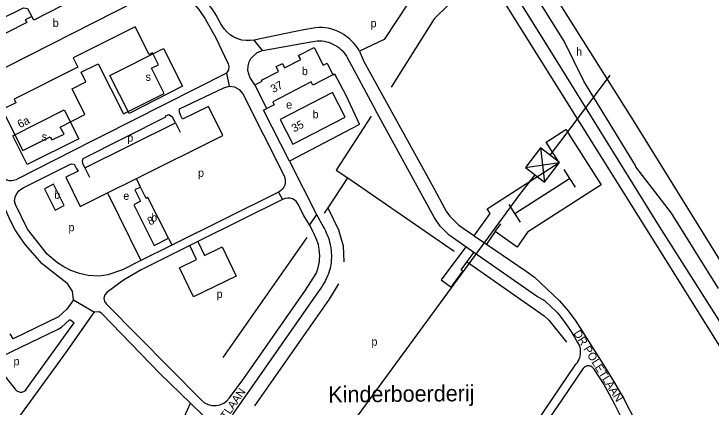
# Model space of a CAD drawing. Extents: x 158142 to 159655, y 385262 to 387204.
# Drawn here: x 159056.3 to 159402.4, y 386220.3 to 386415.6 of the extents above; entities that cross this region are included whole.
import ezdxf

# ---------------------------------------------------------------- set-up
doc = ezdxf.new("R2010")
doc.units = 0
for name, color, linetype in [('BLT_Basislijn', 7, 'Continuous'), ('BLT_Bebouwing', 7, 'Continuous'), ('BLT_Centroide', 7, 'Continuous'), ('BLT_Hoogspanningsmast_en_leidingen', 7, 'Continuous'), ('BLT_Huisnummer', 7, 'Continuous'), ('BLT_Huisnummer_zonder_bebouwing', 7, 'Continuous'), ('BLT_Plantopo', 7, 'Continuous'), ('BLT_Straatnaam_verkleind', 7, 'Continuous'), ('BLT_Terrein_beschrifting', 7, 'Continuous'), ('BLT_Vlakafsluiter', 7, 'Continuous')]:
    doc.layers.add(name, color=color, linetype=linetype)

msp = doc.modelspace()

# ---------------------------------------------------------------- linework, layer by layer
at = {"layer": 'BLT_Basislijn'}
for p, q in [((159227.95, 386397.14), (159229.86, 386392.29)), ((159221.65, 386394.34), (159235.67, 386368.16)), ((159091.61, 386339.19), (159136.59, 386361.56)), ((159136.59, 386361.56), (159138.94, 386356.79)), ((159193.2, 386342.48), (159206.56, 386316.04)), ((159091.61, 386339.19), (159093.91, 386334.54)), ((159329.32, 386338.29), (159332.13, 386333.91)), ((159119.2, 386329.59), (159117.12, 386333.8)), ((159222, 386334.21), (159212.14, 386319.33)), ((159222.04, 386334.14), (159274.93, 386297.82)), ((159305.02, 386316.48), (159332.13, 386333.91)), ((159332.13, 386333.91), (159334.95, 386329.53)), ((159102.79, 386326.67), (159119.38, 386293.11)), ((159305.02, 386316.48), (159302.2, 386320.86)), ((159212.14, 386319.33), (159210.35, 386316.62)), ((159307.83, 386312.1), (159305.02, 386316.48)), ((159295.31, 386307.53), (159298.04, 386311.37)), ((159295.31, 386307.53), (159290.87, 386301.25)), ((159133.08, 386304.14), (159134.75, 386300.77)), ((159160.16, 386244.92), (159201.9, 386304.56)), ((159284.86, 386305.35), (159290.87, 386301.25)), ((159147.69, 386302.57), (159143.71, 386300.59)), ((159284.71, 386297.1), (159280.61, 386299.95)), ((159278.34, 386288.55), (159284.71, 386297.1)), ((159062.18, 386228.82), (159086.31, 386262.11)), ((159049.87, 386238.11), (159056.95, 386229.28)), ((159344.23, 386239.16), (159349.21, 386231.63))]:
    msp.add_line(p, q, dxfattribs=at)
for points in [[(159478.02, 386149.53), (159467.1, 386166.67), (159451.19, 386191.65), (159448.58, 386196.2), (159403.98, 386267.32), (159376.84, 386309.95), (159320.35, 386401.06), (159194.99, 386601.74), (159190.31, 386604.18), (159180.82, 386620.38), (159176.63, 386631.64), (159172.66, 386639.08), (159146.46, 386681.4), (159151.12, 386684.55)], [(159413.02, 386283.52), (159409.77, 386288.65), (159364.7, 386361.34), (159326.64, 386421.78), (159323.99, 386426.39), (159205.26, 386616.42)], [(159406.2, 386279.27), (159382.73, 386316.66), (159365.07, 386339.65), (159364.85, 386340.38), (159339.3, 386382.12), (159329.59, 386402.01), (159197.96, 386612.2)], [(159115.71, 386445.71), (159116.77, 386445.89), (159117.81, 386445.92), (159118.97, 386445.78), (159120.27, 386445.46), (159132.43, 386434.32), (159132.87, 386433.9), (159140.84, 386426.2), (159148.13, 386417.86), (159151.35, 386413.14), (159156.54, 386403.77)], [(159283.65, 386446.69), (159288.31, 386439.83), (159375.73, 386300.12)], [(159159.7, 386409.64), (159159.41, 386410.19), (159159.12, 386410.72), (159158.09, 386412.56), (159156.72, 386414.9), (159155.38, 386417.04), (159153.14, 386420.28), (159149.94, 386424.39), (159148.22, 386426.41), (159146.03, 386428.81), (159143.45, 386431.45)], [(159251.36, 386433.07), (159252.44, 386421.45), (159240.13, 386402.93), (159227.95, 386397.14)], [(159277.97, 386429.97), (159272.13, 386420.08), (159264.98, 386413.18), (159243.67, 386379.17)], [(159023.64, 386400.21), (159061.09, 386418.61), (159063, 386418.33), (159065.21, 386414.36)], [(159175.58, 386402.58), (159173.63, 386402.31), (159171.59, 386402.31), (159169.53, 386402.59), (159167.49, 386403.17), (159165.55, 386404.04), (159163.76, 386405.16), (159162.17, 386406.5), (159160.81, 386408.02), (159159.7, 386409.64)], [(159206.06, 386408.7), (159200.25, 386407.61), (159195.32, 386406.62), (159179.43, 386403.35), (159175.58, 386402.58)], [(159220.05, 386405.32), (159218.68, 386406.17), (159217.23, 386406.91), (159215.72, 386407.54), (159214.16, 386408.05), (159212.55, 386408.44), (159210.93, 386408.7), (159209.29, 386408.83), (159207.67, 386408.83), (159206.06, 386408.7)], [(159156.54, 386403.77), (159160.84, 386394.55), (159162.74, 386390.86), (159162.98, 386389.41), (159162.93, 386387.85), (159161.92, 386386.1)], [(159227.95, 386397.14), (159227.28, 386398.21), (159226.54, 386399.25), (159225.75, 386400.26), (159224.91, 386401.22), (159224.02, 386402.14), (159223.09, 386403.01), (159222.11, 386403.84), (159221.1, 386404.61), (159220.05, 386405.32)], [(159179.8, 386397.43), (159204.7, 386401.94)], [(159204.7, 386401.94), (159205.83, 386402.11), (159206.96, 386402.2), (159208.1, 386402.22), (159209.24, 386402.15), (159210.37, 386402.01), (159211.49, 386401.78), (159212.59, 386401.48), (159213.66, 386401.1), (159214.7, 386400.65), (159215.71, 386400.12), (159216.68, 386399.53), (159217.61, 386398.86), (159218.49, 386398.14), (159219.32, 386397.36), (159220.08, 386396.51), (159220.79, 386395.62), (159221.43, 386394.68), (159221.65, 386394.34)], [(159175.96, 386380.29), (159173.43, 386384.14), (159172.52, 386387.51), (159172.58, 386389.81), (159173.09, 386391.85), (159173.96, 386393.43), (159177.1, 386396.35), (159179.8, 386397.43)], [(159229.86, 386392.29), (159263.98, 386330.56), (159271.1, 386317.22), (159272.68, 386315.21), (159277.17, 386310.63), (159284.11, 386305.86), (159284.86, 386305.35)], [(159161.92, 386386.1), (159100, 386354.94), (159095.08, 386352.41), (159058, 386333.55)], [(159214.72, 386385.36), (159215.57, 386385.8), (159221.04, 386375.18), (159227.78, 386361.06), (159227.53, 386360.58), (159193.2, 386342.48)], [(159117.12, 386333.8), (159160.1, 386355.17), (159152.89, 386369.67), (159140.01, 386363.26), (159139.15, 386364.93), (159138.49, 386366.83), (159138.56, 386368.38), (159160.56, 386378.95), (159163.21, 386379.67)], [(159163.21, 386379.67), (159165.9, 386379.35), (159168.21, 386378.08), (159169.96, 386375.85), (159190.43, 386335.21), (159190.83, 386334.19), (159191.07, 386333.04), (159191.06, 386331.72), (159190.76, 386330.62), (159190.33, 386329.58), (159189.58, 386328.52), (159188.69, 386327.71), (159187.74, 386327.14)], [(159136.59, 386361.56), (159135.12, 386364.35), (159133.19, 386365.55), (159131.35, 386364.73), (159131.57, 386364.3), (159090.62, 386343.54), (159090.18, 386342.44), (159090.39, 386341.36), (159091.61, 386339.19)], [(159193.2, 386342.48), (159180.17, 386367.75), (159181.91, 386368.63)], [(159280.61, 386299.95), (159272.4, 386305.67), (159268.03, 386310.22), (159265.21, 386314.38), (159235.67, 386368.16)], [(159233.7, 386364.79), (159216.33, 386338.06), (159222.04, 386334.14)], [(159284.86, 386305.35), (159292.74, 386316.48), (159291.29, 386318.74), (159327.09, 386341.75), (159320.56, 386351.91), (159330.29, 386358.16), (159347.95, 386330.69), (159311.31, 386307.14), (159306.25, 386299.78), (159295.31, 386307.53)], [(159119.38, 386293.11), (159110.16, 386288.53), (159102.96, 386286.02), (159098.67, 386285.3), (159093.27, 386285.73), (159088.94, 386286.69), (159084.64, 386288.21), (159081.08, 386289.98), (159077.97, 386292.05), (159072.88, 386296.34), (159063.13, 386308.66), (159057.06, 386320.95), (159056.68, 386322.72), (159056.95, 386324.58), (159057.55, 386326.11), (159058.82, 386327.71), (159059.68, 386328.4), (159060.89, 386329.16), (159084.82, 386341.2), (159086.29, 386340.89), (159087.3, 386339.04), (159088.18, 386337.48), (159082.08, 386334.44), (159089.29, 386319.95), (159102.79, 386326.67)], [(159049.1, 386336.14), (159049.52, 386335.53), (159050.01, 386334.97), (159050.55, 386334.46), (159051.15, 386334.01), (159051.79, 386333.64), (159052.46, 386333.33), (159053.17, 386333.1), (159053.9, 386332.94), (159054.64, 386332.86), (159055.38, 386332.86), (159056.12, 386332.95), (159056.85, 386333.11), (159057.55, 386333.35), (159058, 386333.55)], [(159102.79, 386326.67), (159117.12, 386333.8)], [(159187.74, 386327.14), (159134.75, 386300.77)], [(159203.04, 386310.87), (159201.77, 386313.01), (159200.18, 386315.61), (159197.68, 386320.82), (159196.38, 386322.54), (159194.56, 386323.68), (159193.46, 386324.01), (159192.32, 386324.12), (159190.95, 386323.96), (159189.65, 386323.49)], [(159085.99, 386273.53), (159085.48, 386277.83), (159083.09, 386281.45), (159081.81, 386282.5), (159078.95, 386284.67), (159070.33, 386291.47), (159062.1, 386300.83), (159059.2, 386304.92), (159056.96, 386308.41), (159054.43, 386313.15), (159051.66, 386319.56), (159049.99, 386321.42), (159047.94, 386321.62)], [(159189.65, 386323.49), (159147.69, 386302.57)], [(159212.14, 386319.33), (159217.5, 386308.34), (159219.78, 386300.37), (159220.12, 386292.42)], [(159206.56, 386316.04), (159210.01, 386309.62), (159210.48, 386308.82), (159210.95, 386307.91), (159211.21, 386307.36), (159211.57, 386306.57), (159211.9, 386305.8), (159212.21, 386304.98), (159212.45, 386304.31), (159212.76, 386303.38), (159213.05, 386302.28), (159213.32, 386301.14), (159213.46, 386300.45), (159213.64, 386299.33), (159213.82, 386297.94), (159213.9, 386296.7), (159213.93, 386296.09), (159213.94, 386294.76), (159213.88, 386293.42), (159213.77, 386292.03), (159213.66, 386291.18), (159213.49, 386290.19), (159213.26, 386289.25), (159212.96, 386288.19)], [(159170.43, 386234.47), (159181.31, 386250), (159201.15, 386278.33), (159206.36, 386286.67), (159206.74, 386287.57), (159207.05, 386288.43), (159207.42, 386289.61), (159207.75, 386291.08), (159208.01, 386292.65), (159208.12, 386293.64), (159208.2, 386295.25), (159208.12, 386297.25), (159207.95, 386298.66), (159207.73, 386299.93), (159207.51, 386300.87), (159207.22, 386301.95), (159206.79, 386303.22), (159206.29, 386304.45), (159205.58, 386305.87), (159204.49, 386307.98), (159203.04, 386310.87)], [(159143.71, 386300.59), (159119.46, 386288.5), (159110.67, 386283.29), (159102.42, 386277.24), (159101.39, 386276), (159100.97, 386274.37), (159101.27, 386272.73), (159102.23, 386271.42), (159149.52, 386223.73), (159151, 386222.49), (159152.85, 386221.58), (159154.65, 386221.1), (159156.69, 386221.1), (159158.64, 386221.45), (159160.52, 386222.29), (159162.01, 386223.43), (159163.3, 386224.93)], [(159134.75, 386300.77), (159119.38, 386293.11)], [(159147.69, 386302.57), (159150.98, 386295.61), (159159.65, 386299.84), (159166.65, 386285.38), (159145.54, 386275.04), (159138.48, 386289.49), (159147.03, 386293.6), (159143.71, 386300.59)], [(159280.61, 386299.95), (159268.42, 386283.61), (159273.37, 386279.91)], [(159290.87, 386301.25), (159310.6, 386287.8), (159314.81, 386284.81), (159327.24, 386273.1)], [(159375.73, 386300.12), (159459.1, 386166.67), (159467.97, 386152.7), (159493.65, 386111.16), (159564.29, 385998.58)], [(159326.21, 386267.08), (159325.75, 386267.58), (159319.84, 386273.08), (159315.82, 386275.44), (159284.71, 386297.1)], [(159281.56, 386292.35), (159319.66, 386265.61), (159321.96, 386263.42), (159330.69, 386252.56)], [(159212.96, 386288.19), (159212.66, 386287.23), (159212.29, 386286.2), (159212.05, 386285.53), (159211.37, 386283.99), (159210.86, 386282.95), (159210.36, 386282.04), (159210.07, 386281.54), (159209.38, 386280.4), (159208.7, 386279.39), (159207.91, 386278.3), (159207.4, 386277.57), (159174.39, 386230.39)], [(159273.37, 386279.91), (159279.28, 386287.84), (159278.34, 386288.55)], [(159217.55, 386281.53), (159212.84, 386273.88), (159175.7, 386221)], [(159085.99, 386273.53), (159082.59, 386269.02), (159078.44, 386265.17), (159056.01, 386254.27), (159054.51, 386256.71)], [(159327.24, 386273.1), (159331.5, 386268.16), (159335.22, 386262.97), (159349.8, 386240.06)], [(159096.41, 386267.43), (159095.57, 386266.68), (159081.97, 386247.29), (159055.55, 386210.96)], [(159143.92, 386222.3), (159128.86, 386236.84), (159100, 386266.74), (159098.66, 386267.59), (159096.41, 386267.43)], [(159326.21, 386267.08), (159328.04, 386264.76), (159329.8, 386262.4), (159331.5, 386259.98), (159333.14, 386257.53), (159334.7, 386255.02), (159336.2, 386252.48), (159337.02, 386251.02)], [(159050.88, 386245.81), (159078.22, 386259.09), (159079.88, 386260.02), (159084, 386263.59), (159084.5, 386263.61), (159086.31, 386262.11)], [(159337.02, 386251.02), (159337.26, 386250.15), (159337.42, 386249.26), (159337.5, 386248.36), (159337.51, 386247.46), (159337.43, 386246.56), (159337.27, 386245.67), (159337.04, 386244.8), (159336.73, 386243.95), (159336.35, 386243.13), (159335.89, 386242.35), (159335.35, 386241.6)], [(159257.19, 386172.23), (159259.87, 386175.88), (159260.88, 386175.98), (159273.93, 386166.67), (159277.01, 386164.47), (159280.82, 386164.1), (159282.54, 386164.89), (159284.1, 386166.15), (159284.38, 386166.67), (159285.25, 386168.27), (159296.23, 386183.93), (159335.35, 386241.6)], [(159339.27, 386239.78), (159339.58, 386240.14), (159339.94, 386240.45), (159340.35, 386240.69), (159340.8, 386240.86), (159341.27, 386240.95), (159341.74, 386240.96), (159342.21, 386240.9), (159342.67, 386240.75), (159343.09, 386240.53), (159343.47, 386240.24), (159343.8, 386239.9), (159344.07, 386239.5), (159344.23, 386239.16)], [(159310.52, 386197.65), (159328.55, 386223.94), (159339.27, 386239.78)], [(159349.8, 386240.06), (159352.21, 386236.24), (159354.56, 386232.37), (159356.84, 386228.47), (159359.05, 386224.52), (159361.19, 386220.54), (159363.26, 386216.52), (159365.26, 386212.46), (159367.18, 386208.37), (159369.04, 386204.25), (159369.67, 386202.8)], [(159163.3, 386224.93), (159170.43, 386234.47)], [(159349.21, 386231.63), (159351.9, 386226.75), (159354.51, 386221.83), (159357.05, 386216.87), (159359.52, 386211.88), (159361.92, 386206.85), (159364.25, 386201.79), (159365.25, 386199.55)], [(159062.18, 386228.82), (159061.84, 386228.45), (159061.45, 386228.14), (159061.01, 386227.9), (159060.54, 386227.73), (159060.04, 386227.64), (159059.54, 386227.63), (159059.05, 386227.7), (159058.57, 386227.84), (159058.12, 386228.06), (159057.71, 386228.35), (159057.35, 386228.7), (159057.06, 386229.1), (159056.95, 386229.28)], [(159174.39, 386230.39), (159165.13, 386217.16), (159164.16, 386215.22), (159163.75, 386212.31)], [(159076.26, 386121.76), (159136.31, 386207.61), (159139.47, 386212.15), (159139.54, 386212.34), (159143.92, 386222.3)], [(159152.1, 386211.24), (159151.63, 386214.16), (159150.11, 386216.33), (159143.92, 386222.3)]]:
    msp.add_lwpolyline(points, dxfattribs=at)
for points in [[(159104.01, 386384.99), (159130.62, 386398.42), (159140.1, 386379.65), (159113.49, 386366.21)], [(159055.82, 386354.97), (159081.32, 386367.94), (159088.64, 386353.63), (159062.98, 386340.74)]]:
    msp.add_lwpolyline(points, close=True, dxfattribs=at)
at = {"layer": 'BLT_Bebouwing'}
msp.add_line((159181.91, 386368.63), (159175.96, 386380.29), dxfattribs=at)
for points in [[(159109.65, 386436.3), (159116.99, 386421.94), (159042.48, 386384.25), (159035.14, 386398.75)], [(159079.2, 386421.42), (159080.11, 386419.58), (159066.14, 386412.52), (159065.21, 386414.36)], [(159065.21, 386414.36), (159061.96, 386412.72), (159062.67, 386411.27), (159042.43, 386401.06), (159041.88, 386402.15), (159035.14, 386398.75)], [(159187.77, 386387.04), (159186.54, 386389.44), (159189.62, 386391), (159190.72, 386388.81), (159198.75, 386392.96), (159197.68, 386395.02), (159205.41, 386398.97), (159209.93, 386390.17), (159211.78, 386391.13), (159214.72, 386385.36)], [(159175.96, 386380.29), (159179.62, 386382.18), (159179.33, 386382.74), (159187.77, 386387.04)], [(159214.72, 386385.36), (159204.73, 386380.28), (159203.91, 386381.85), (159184.82, 386371.98), (159185.58, 386370.5), (159181.91, 386368.63)], [(159220.74, 386364.28), (159214.42, 386376.55), (159188.48, 386363.18), (159194.8, 386350.92), (159220.74, 386364.28)], [(159119.2, 386329.59), (159116.41, 386328.19), (159119.24, 386322.57), (159115.81, 386320.84), (159126, 386300.64), (159133.08, 386304.14)], [(159122.86, 386324.4), (159122.03, 386323.98), (159119.2, 386329.59)], [(159133.08, 386304.14), (159122.86, 386324.4)]]:
    msp.add_lwpolyline(points, dxfattribs=at)
msp.add_lwpolyline([(159075.96, 386331.05), (159071.5, 386328.79), (159076.82, 386318.13), (159081.26, 386320.4)], close=True, dxfattribs=at)
at = {"layer": 'BLT_Hoogspanningsmast_en_leidingen'}
for p, q in [((159330.03, 386355.19), (159352.36, 386385.16)), ((159322.53, 386345.42), (159330.03, 386355.19)), ((159317.8, 386349.06), (159319.76, 386332.02)), ((159310.29, 386339.29), (159327.26, 386341.79)), ((159307.53, 386325.89), (159315.03, 386335.66)), ((159225.57, 386214.03), (159307.53, 386325.89))]:
    msp.add_line(p, q, dxfattribs=at)
msp.add_lwpolyline([(159317.8, 386349.06), (159310.29, 386339.29), (159319.76, 386332.02), (159327.26, 386341.79)], close=True, dxfattribs=at)
at = {"layer": 'BLT_Plantopo'}
msp.add_lwpolyline([(159116.59, 386409.22), (159085.8, 386393.7), (159088.1, 386389.15), (159056.43, 386373.19), (159057.32, 386371.38), (159050.57, 386368.04), (159060.77, 386347.79), (159074.31, 386354.62), (159075.09, 386353.07), (159081.2, 386355.82), (159079.32, 386359.4), (159091.59, 386365.71), (159085.18, 386378.43), (159092.11, 386381.91), (159089.73, 386386.63), (159098.15, 386390.88), (159110.74, 386365.89), (159130.93, 386376.07), (159124.61, 386388.59), (159128.07, 386390.33), (159125.08, 386396.27), (159123.52, 386395.49)], close=True, dxfattribs=at)
at = {"layer": 'BLT_Vlakafsluiter'}
for p, q in [((159179.8, 386397.43), (159175.58, 386402.58)), ((159161.92, 386386.1), (159163.21, 386379.67)), ((159187.74, 386327.14), (159189.65, 386323.49)), ((159206.56, 386316.04), (159203.04, 386310.87)), ((159085.99, 386273.53), (159096.41, 386267.43))]:
    msp.add_line(p, q, dxfattribs=at)

# ---------------------------------------------------------------- texts
at = {"layer": 'BLT_Centroide'}
for s, p in [('b', (159075.6, 386409.12)), ('p', (159233.42, 386408.98)), ('h', (159335.46, 386394.87)), ('b', (159199.27, 386385.19)), ('s', (159121.69, 386382.37)), ('e', (159191.49, 386368.56)), ('b', (159204.61, 386363.72)), ('s', (159070.14, 386352.66)), ('p', (159112.62, 386352.13)), ('p', (159147.74, 386334.7)), ('b', (159076.31, 386323.77)), ('e', (159110.64, 386323.28)), ('b', (159124.45, 386312.48)), ('p', (159083.41, 386307.63)), ('p', (159156.94, 386274.54)), ('p', (159233.83, 386250.86)), ('p', (159056.11, 386241.1))]:
    msp.add_text(s, height=4, dxfattribs=at).set_placement(p)
at = {"layer": 'BLT_Huisnummer'}
for s, p in [('37', (159185.07, 386376.23)), ('35', (159195.45, 386356.68)), ('8', (159123.87, 386310.45))]:
    msp.add_text(s, height=4, rotation=27.8253, dxfattribs=at).set_placement(p)
at = {"layer": 'BLT_Huisnummer_zonder_bebouwing'}
msp.add_text('6a', height=4, rotation=27.8253, dxfattribs=at).set_placement((159059.35, 386358.73))
at = {"layer": 'BLT_Straatnaam_verkleind'}
for rotation, p in [(302.007, (159333.99, 386257.02)), (55.2331, (159148.37, 386194.51))]:
    msp.add_text('DR POLETLAAN', height=4, rotation=rotation, dxfattribs=at).set_placement(p)
at = {"layer": 'BLT_Terrein_beschrifting'}
msp.add_text('Kinderboerderij', height=8, rotation=0.5533, dxfattribs=at).set_placement((159212.46, 386222.59))

doc.saveas('drawing.dxf')
